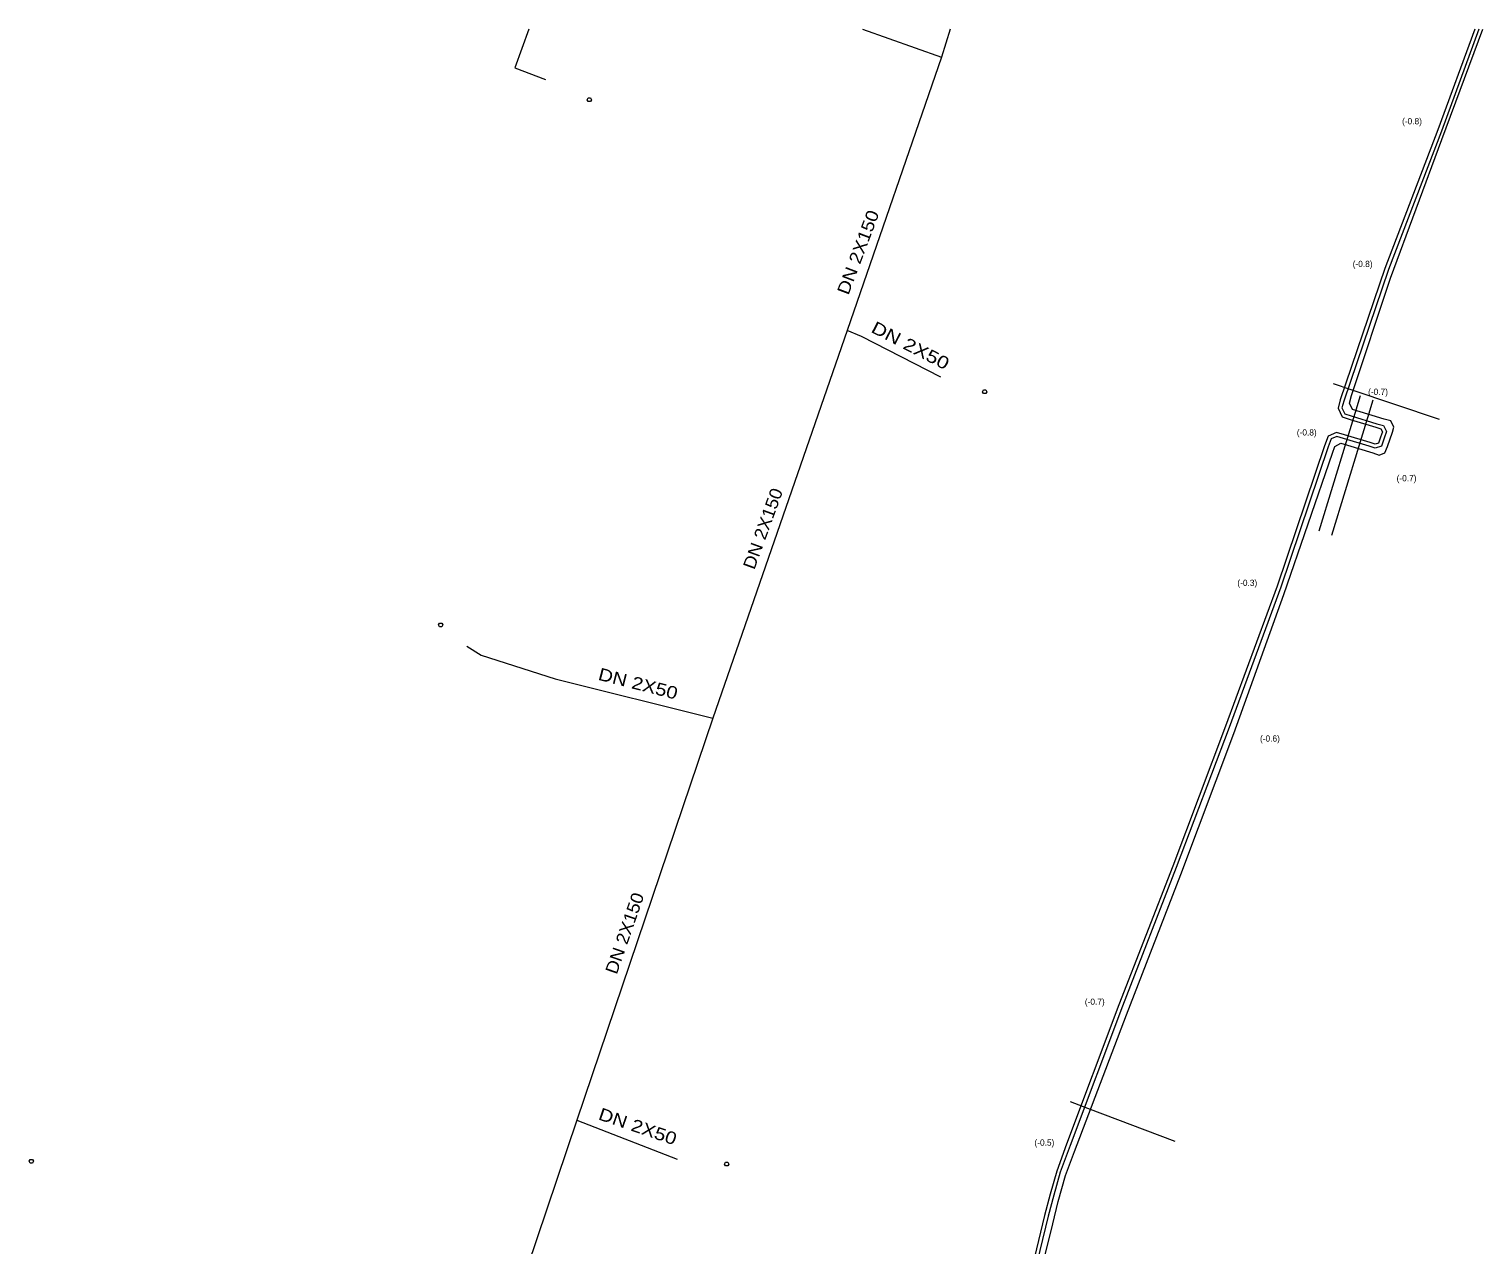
# Model space of a CAD drawing. Extents: x -725606 to -725269, y -977352 to -977136.
# Drawn here: x -725385.7 to -725268.8, y -977233.9 to -977136.2 of the extents above; entities that cross this region are included whole.
import ezdxf
from ezdxf.enums import TextEntityAlignment as Align

# ---------------------------------------------------------------- set-up
doc = ezdxf.new("R2010")
doc.units = 0
doc.header["$LTSCALE"] = 0.2
doc.layers.add('46', color=7, linetype='Continuous')
for name, color, linetype, lineweight in [('47', 7, 'Continuous', 13), ('48', 7, 'Continuous', 13), ('63', 7, 'Continuous', 13)]:
    doc.layers.add(name, color=color, linetype=linetype, lineweight=lineweight)

msp = doc.modelspace()

# ---------------------------------------------------------------- linework, layer by layer
at = {"layer": '47'}
for points in [[(-725280.89, -977164.67), (-725279.47, -977165.15), (-725272.36, -977167.54)], [(-725280.98, -977176.87), (-725278.79, -977169.7), (-725278.1, -977167.41), (-725277.66, -977165.98)], [(-725302.02, -977222.39), (-725300.62, -977222.92), (-725293.6, -977225.57)]]:
    msp.add_lwpolyline(points, dxfattribs=at)
at = {"layer": '48'}
msp.add_lwpolyline([(-725278.7, -977165.66), (-725279.14, -977167.1), (-725279.83, -977169.38), (-725282.02, -977176.55)], dxfattribs=at)
at = {"layer": '63'}
for p, q in [((-725311.656, -977136.198), (-725312.361, -977138.456)), ((-725341.66, -977223.886), (-725333.597, -977227.021))]:
    msp.add_line(p, q, dxfattribs=at)
for points in [[(-725345.522, -977136.198), (-725346.67, -977139.3), (-725344.189, -977140.249)], [(-725318.702, -977136.198), (-725312.361, -977138.456), (-725319.955, -977160.421)], [(-725269.498, -977136.198), (-725272.461, -977144.285), (-725276.722, -977155.428), (-725280.318, -977166.004), (-725280.488, -977166.661), (-725280.155, -977167.355), (-725279.51, -977167.566), (-725277.445, -977168.198), (-725277.048, -977168.312), (-725276.924, -977168.555), (-725277.065, -977168.987), (-725277.226, -977169.477), (-725277.497, -977169.557), (-725277.892, -977169.433), (-725279.964, -977168.803), (-725280.612, -977168.61), (-725281.29, -977168.92), (-725281.563, -977169.681), (-725285.373, -977180.96), (-725289.521, -977192.225), (-725293.77, -977203.463), (-725298.1, -977214.603), (-725302.301, -977225.806), (-725303.096, -977227.977), (-725303.619, -977229.82), (-725304.081, -977231.536), (-725305.86, -977238.905)], [(-725269.179, -977136.198), (-725272.18, -977144.39), (-725276.44, -977155.53), (-725280.03, -977166.09), (-725280.17, -977166.63), (-725279.94, -977167.11), (-725279.42, -977167.28), (-725277.36, -977167.91), (-725276.84, -977168.06), (-725276.6, -977168.53), (-725276.78, -977169.08), (-725276.99, -977169.72), (-725277.5, -977169.87), (-725277.98, -977169.72), (-725280.05, -977169.09), (-725280.59, -977168.93), (-725281.05, -977169.14), (-725281.28, -977169.78), (-725285.09, -977181.06), (-725289.24, -977192.33), (-725293.49, -977203.57), (-725297.82, -977214.71), (-725302.02, -977225.91), (-725302.81, -977228.07), (-725303.33, -977229.9), (-725303.79, -977231.61), (-725305.57, -977238.98)], [(-725305.17, -977239.35), (-725303.41, -977232.22), (-725302.99, -977230.42), (-725302.39, -977228.32), (-725301.66, -977226.39), (-725297.49, -977215.42), (-725293.13, -977204.13), (-725288.85, -977192.82), (-725284.84, -977181.65), (-725280.94, -977170.28), (-725280.74, -977169.75), (-725280.27, -977169.48), (-725279.72, -977169.63), (-725277.7, -977170.26), (-725277.17, -977170.43), (-725276.73, -977170.26), (-725276.52, -977169.74), (-725276.11, -977168.6), (-725276, -977168.2), (-725276.25, -977167.69), (-725276.79, -977167.54), (-725278.71, -977166.97), (-725279.33, -977166.77), (-725279.57, -977166.27), (-725279.4, -977165.65), (-725276.26, -977156.22), (-725272.14, -977145.07), (-725268.84, -977136.198)], [(-725312.414, -977164.169), (-725318.784, -977160.911), (-725319.955, -977160.421), (-725330.746, -977191.568)], [(-725350.511, -977185.787), (-725349.36, -977186.525), (-725343.402, -977188.408), (-725330.746, -977191.568), (-725341.66, -977223.886), (-725354.485, -977261.861), (-725355.226, -977264.237)]]:
    msp.add_lwpolyline(points, dxfattribs=at)
for points in [[(-725340.584, -977141.723), (-725340.494, -977141.873), (-725340.584, -977142.023), (-725340.764, -977142.023), (-725340.854, -977141.873), (-725340.764, -977141.723)], [(-725308.807, -977165.197), (-725308.717, -977165.347), (-725308.807, -977165.497), (-725308.987, -977165.497), (-725309.077, -977165.347), (-725308.987, -977165.197)], [(-725352.529, -977183.93), (-725352.439, -977184.08), (-725352.529, -977184.23), (-725352.709, -977184.23), (-725352.799, -977184.08), (-725352.709, -977183.93)], [(-725385.433, -977227.039), (-725385.343, -977227.189), (-725385.433, -977227.339), (-725385.613, -977227.339), (-725385.703, -977227.189), (-725385.613, -977227.039)], [(-725329.541, -977227.265), (-725329.451, -977227.415), (-725329.541, -977227.565), (-725329.721, -977227.565), (-725329.811, -977227.415), (-725329.721, -977227.265)]]:
    msp.add_lwpolyline(points, close=True, dxfattribs=at)

# ---------------------------------------------------------------- texts
at = {"layer": '46'}
for s, p in [('(-0.8)', (-725274.54, -977143.85)), ('(-0.8)', (-725278.51, -977155.32)), ('(-0.7)', (-725277.27, -977165.6)), ('(-0.8)', (-725283, -977168.86)), ('(-0.7)', (-725274.98, -977172.54)), ('(-0.3)', (-725287.78, -977180.95)), ('(-0.6)', (-725285.96, -977193.46)), ('(-0.7)', (-725300.04, -977214.61)), ('(-0.5)', (-725304.09, -977225.93))]:
    msp.add_text(s, height=0.5, dxfattribs=at).set_placement(p, align=Align.CENTER)
at = {"layer": '63'}
for s, rotation, width, p in [('DN 2X150', 69.328, 1.15, (-725318.5958, -977154.311)), ('DN 2X50', 332.831, 1.25, (-725315.0818, -977162.068)), ('DN 2X150', 70.015, 1.1, (-725326.2464, -977176.5109)), ('DN 2X50', 345.723, 1.2, (-725336.8698, -977189.2832)), ('DN 2X150', 70.818, 1.1, (-725337.3548, -977209.0228)), ('DN 2X50', 341.196, 1.2, (-725336.9362, -977224.856))]:
    msp.add_text(s, height=1, rotation=rotation, dxfattribs=dict(at, width=width)).set_placement(p, align=Align.CENTER)

doc.saveas('drawing.dxf')
